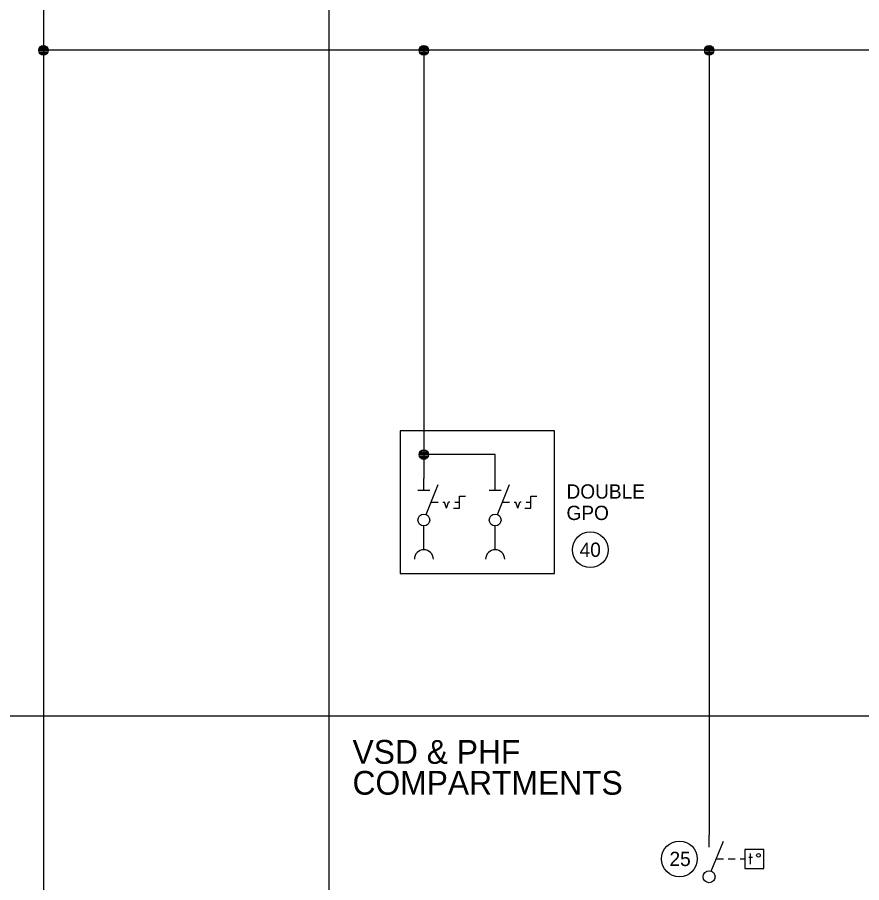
# Model space of a CAD drawing. Extents: x 0 to 841, y 0 to 594.
# Drawn here: x 414.5 to 592.1, y 185 to 366.9 of the extents above; entities that cross this region are included whole.
import ezdxf

# ---------------------------------------------------------------- set-up
doc = ezdxf.new("R2010")
doc.units = 0
doc.layers.add('Level 1', color=7, linetype='Continuous')
doc.layers.add('Level 10', color=7, linetype='Continuous')

msp = doc.modelspace()

# ---------------------------------------------------------------- linework, layer by layer
at = {"layer": 'Level 1'}
for p, q in [((420, 475), (420, 105)), ((480, 420), (480, 57)), ((770, 360), (420, 360)), ((500, 360), (500, 270)), ((560, 360), (560, 195)), ((515, 275), (500, 275)), ((515, 270), (515, 275)), ((500, 267.5), (500, 270)), ((515, 267.5), (515, 270)), ((498.75, 267.5), (501.25, 267.5)), ((500.46, 262.41), (503, 268.75)), ((513.75, 267.5), (516.25, 267.5)), ((515.46, 262.41), (518, 268.75)), ((500, 255), (500, 260)), ((515, 255), (515, 260)), ((829, 220), (28, 220)), ((560, 192.5), (560, 195)), ((560.46, 187.41), (563, 193.75)), ((561.5, 190), (563, 190)), ((564, 190), (565.5, 190)), ((566.5, 190), (567.5, 190))]:
    msp.add_line(p, q, dxfattribs=at)
for points in [[(495, 250), (527.5, 250), (527.5, 280), (495, 280)], [(567.5, 188), (571.5, 188), (571.5, 192), (567.5, 192)]]:
    msp.add_lwpolyline(points, close=True, dxfattribs=at)
for points in [[(568.63, 191.13), (568.63, 188.87)], [(570.36, 190.38), (570.18, 190.42), (570.05, 190.56), (569.99, 190.76), (570.05, 190.94), (570.18, 191.07), (570.36, 191.13), (570.56, 191.07), (570.7, 190.94), (570.74, 190.76), (570.7, 190.56), (570.56, 190.42), (570.36, 190.38)], [(568.38, 190.38), (569.13, 190.38)]]:
    msp.add_lwpolyline(points, dxfattribs=at)
for centre, radius in [((500, 261.25), 1.25), ((515, 261.25), 1.25), ((535, 255), 3.75), ((553.75, 190), 3.75), ((560, 186.25), 1.25)]:
    msp.add_circle(centre, radius, dxfattribs=at)
at = {"layer": 'Level 10'}
for p, q in [((419.05, 360.3), (420.95, 360.3)), ((419.2, 360.6), (420.8, 360.6)), ((419.56, 360.9), (420.44, 360.9)), ((420, 361), (420, 361)), ((499.05, 360.3), (500.95, 360.3)), ((499.2, 360.6), (500.8, 360.6)), ((499.56, 360.9), (500.44, 360.9)), ((500, 361), (500, 361)), ((559.05, 360.3), (560.95, 360.3)), ((559.2, 360.6), (560.8, 360.6)), ((559.56, 360.9), (560.44, 360.9)), ((560, 361), (560, 361)), ((419, 360), (420.99, 360)), ((419.05, 359.7), (420.95, 359.7)), ((419.2, 359.4), (420.8, 359.4)), ((419.56, 359.1), (420.44, 359.1)), ((499, 360), (500.99, 360)), ((499.05, 359.7), (500.95, 359.7)), ((499.2, 359.4), (500.8, 359.4)), ((499.56, 359.1), (500.44, 359.1)), ((559, 360), (560.99, 360)), ((559.05, 359.7), (560.95, 359.7)), ((559.2, 359.4), (560.8, 359.4)), ((559.56, 359.1), (560.44, 359.1)), ((499, 275), (500.99, 275)), ((499.05, 275.3), (500.95, 275.3)), ((499.2, 275.6), (500.8, 275.6)), ((499.56, 275.9), (500.44, 275.9)), ((500, 276), (500, 276)), ((499.05, 274.7), (500.95, 274.7)), ((499.2, 274.4), (500.8, 274.4)), ((499.56, 274.1), (500.44, 274.1)), ((507.5, 263.75), (507.5, 266.25)), ((507.5, 266.25), (508.75, 266.25)), ((522.5, 263.75), (522.5, 266.25)), ((522.5, 266.25), (523.75, 266.25)), ((501.5, 265), (503, 265)), ((504, 265), (504.33, 265)), ((504.75, 263.75), (504.33, 265)), ((504.75, 263.75), (505.17, 265)), ((505.5, 265), (505.17, 265)), ((506.5, 265), (507.5, 265)), ((516.5, 265), (518, 265)), ((519, 265), (519.33, 265)), ((519.75, 263.75), (519.33, 265)), ((519.75, 263.75), (520.17, 265)), ((520.5, 265), (520.17, 265)), ((521.5, 265), (522.5, 265)), ((506.25, 263.75), (507.5, 263.75)), ((521.25, 263.75), (522.5, 263.75))]:
    msp.add_line(p, q, dxfattribs=at)
for centre in [(420, 360), (500, 360), (560, 360), (500, 275)]:
    msp.add_circle(centre, 1, dxfattribs=at)
for centre in [(500, 253), (515, 253)]:
    msp.add_arc(centre, 2, 0, 180, dxfattribs=at)

# ---------------------------------------------------------------- texts
at = {"layer": 'Level 1'}
for s, height, p in [('DOUBLE', 3, (530, 265.75)), ('GPO', 3, (530, 261.25)), ('40', 3, (532.76, 253.5)), ('VSD & PHF', 5, (485, 210)), ('COMPARTMENTS', 5, (485, 203.5)), ('25', 3, (551.66, 188.5))]:
    msp.add_text(s, height=height, dxfattribs=at).set_placement(p)

doc.saveas('drawing.dxf')
